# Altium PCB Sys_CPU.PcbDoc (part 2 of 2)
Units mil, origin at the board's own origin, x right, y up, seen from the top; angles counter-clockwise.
Board outline 2999.97 x 2496.97 mil, 4 copper layers (Top Layer, GND, POWER, Bottom Layer); 73 components, 87 nets, 428 pads, 131 vias.
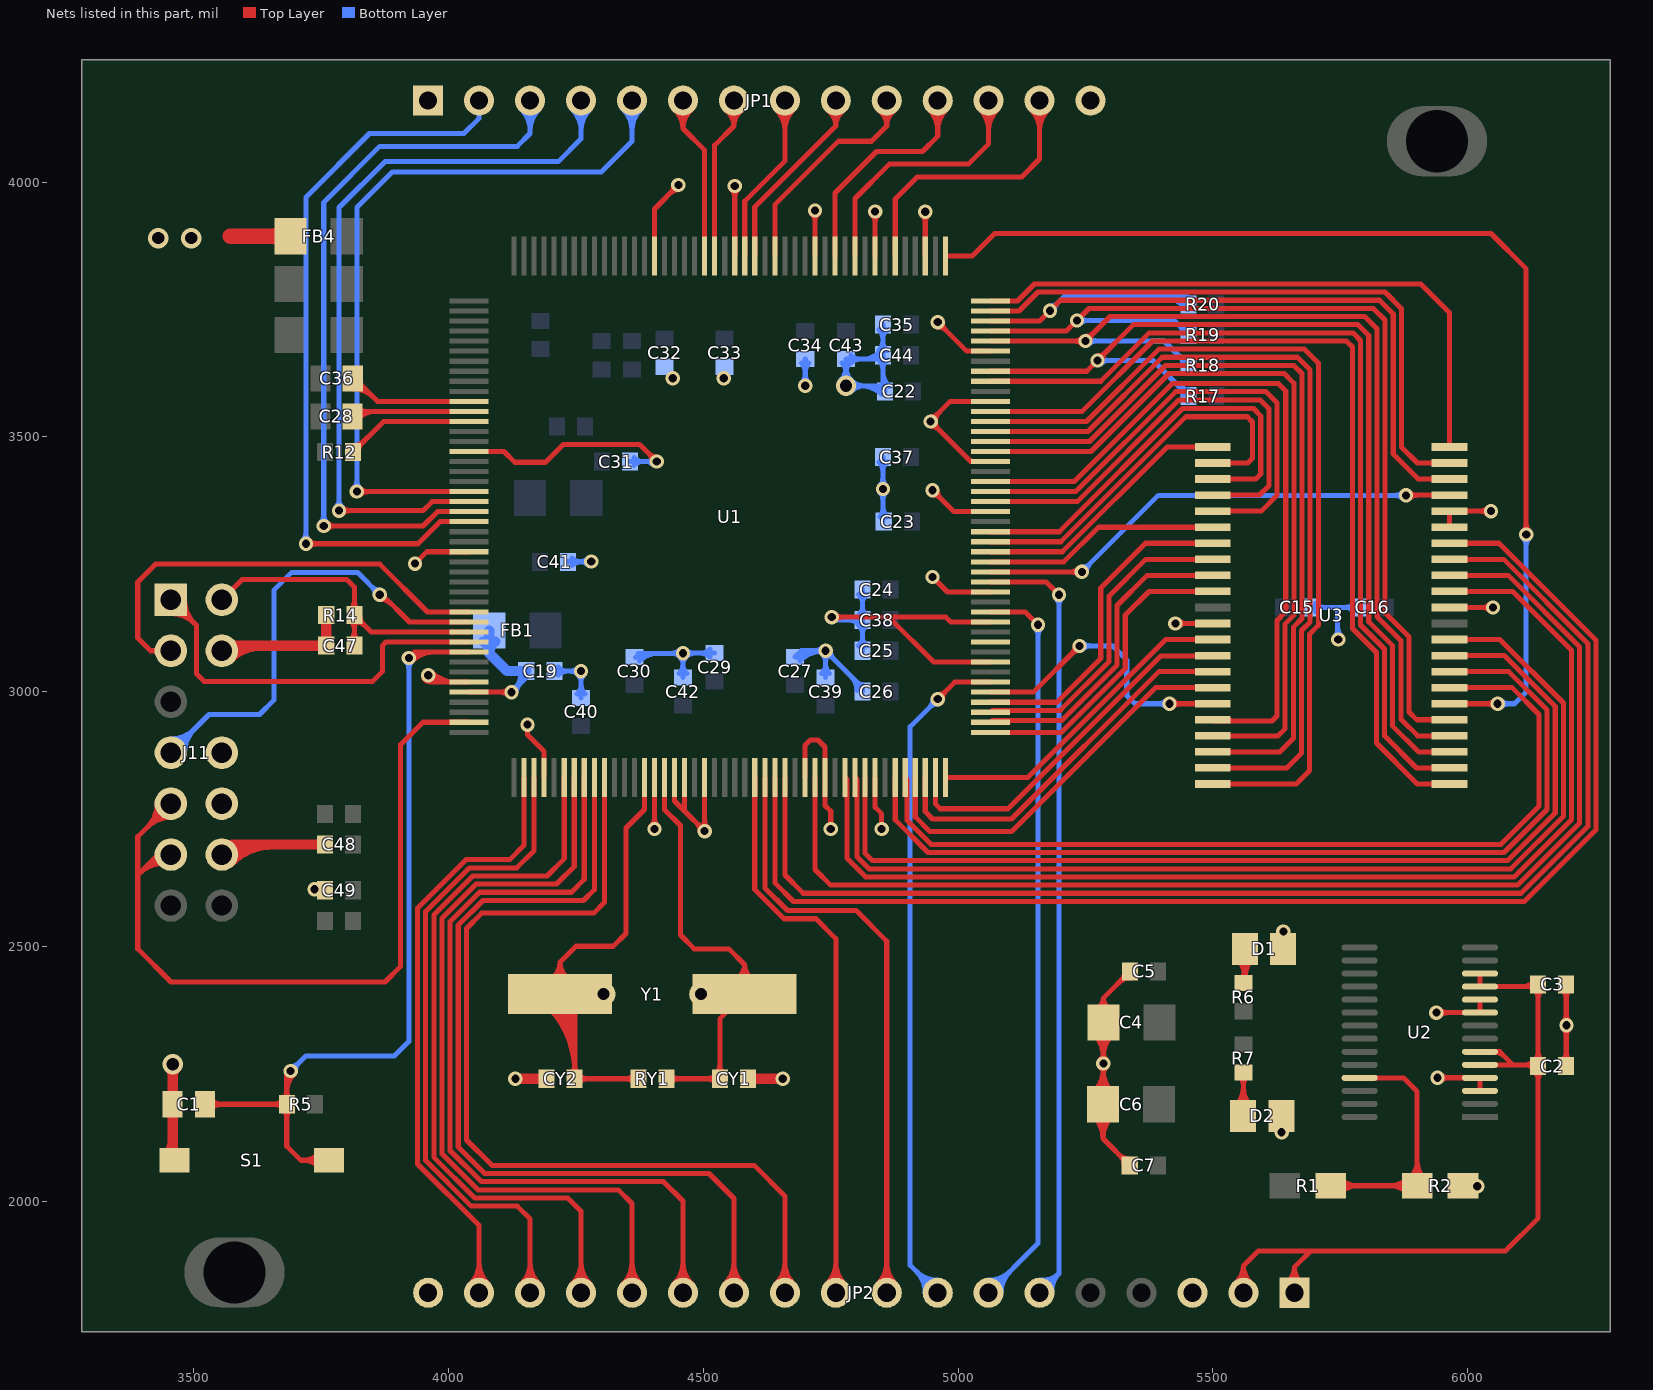
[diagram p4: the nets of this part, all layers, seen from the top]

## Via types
v1: diameter 28, hole 16, Top Layer to Bottom Layer, 105 vias
v2: diameter 40, hole 24, Top Layer to Bottom Layer, 25 vias
v3: diameter 40, hole 24, Top Layer to Bottom Layer, tented bottom, 1 vias

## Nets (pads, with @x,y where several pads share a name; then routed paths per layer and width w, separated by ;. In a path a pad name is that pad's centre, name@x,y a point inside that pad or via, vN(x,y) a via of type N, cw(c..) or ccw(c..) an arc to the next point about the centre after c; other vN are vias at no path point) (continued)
GND: C1.1 C2.1 C3.1 C4.2 C5.2 C6.2 C7.2 C15.1 C16.1 C19.1 C22.1 C23.1 C24.1 C25.1 C26.1 C27.1 C29.1 C30.1 C31.1 C32.1 C33.1 C34.1 C35.1 C37.1 C38.1 C39.1 C40.1 C41.1 C42.1 C43.1 C44.1 C47.1 C48.1 C49.1 CY1.1 CY2.1 D1.2 D2.2 FB4.1 J11.4 J11.8 J11.10 J11.12 JP1.1 JP1.14 JP2.3 JP2.18 R2.2 R14.2 S1.2 U1.3 U1.8 U1.14 U1.22 U1.30 U1.60 U1.70 U1.83 U1.92 U1.103 U1.105 U1.106 U1.108 U1.118 U1.120 U1.125 U1.140 U1.144 U1.147 U1.155 U1.160 U1.166 U1.171 U2.3 U2.4 U2.9 U2.10 U3.12 U3.34 U3.39 U3.40 | length 10653.8
  Top Layer w10: v1(3934,3251) 3957.29,3274.29 U1.70@4039.97,3274.29 ; v1@3952.22,3024.22 ccw(c3966.31,3038.31) 3966.31,3018.39 ; v1@3959.29,3031.29 ccw(c3990.45,3062.45) 3990.45,3018.39 ; v1@3966.36,3038.36 ccw(c4014.59,3086.59) U1.83@4014.59,3018.39 ; 3969,3018.39 U1.83@4039.97,3018.39 ; U1.60@4039.97,3471.14 4108.86,3471.14 4130,3450 4190,3450 4225,3485 4375,3485 v1(4408.54,3451.46) ; v1(4155,2935) 4155,2915 4187.6,2882.4 U1.92@4187.6,2831.38 ; v1@4397.77,2736.36 ccw(c4382.41,2751.73) 4404.14,2751.73 ccw(c4425.87,2751.73) v1@4410.5,2736.36 ; v1@4399.54,3451.46 ccw(c4377.81,3451.46) 4393.18,3466.82 ccw(c4408.54,3482.19) v1@4408.54,3460.46 ; v1(4404.14,2730) U1.103@4404.14,2831.38 ; U1.30@4404.14,3855 4404.14,3947.14 v1(4451,3994) ; v1@4442,3994 cw(c4420.27,3994) 4435.64,3978.64 cw(c4451,3963.27) v1@4451,3985 ; U1.105@4443.51,2831.38 4443.51,2785.06 4463.19,2765.37 ; U1.106@4463.19,2831.38 4463.19,2765.37 ; v1@4493.56,2726 ccw(c4471.84,2726) 4487.2,2741.36 ccw(c4502.56,2756.73) v1@4502.56,2735 ; v1@4496.2,2732.36 ccw(c4480.84,2747.73) 4502.56,2747.73 ccw(c4524.29,2747.73) v1@4508.93,2732.36 ; U1.108@4502.56,2831.38 v1(4502.56,2726) 4463.19,2765.37 ; v1@4555.25,3985.64 cw(c4539.89,3970.27) 4561.62,3970.27 cw(c4583.35,3970.27) v1@4567.98,3985.64 ; U1.22@4561.62,3855 v1(4561.62,3992) ; U1.118@4699.41,2831.38 4699.41,2894.41 4710,2905 4725,2905 4738.78,2891.22 U1.120@4738.78,2831.38 4738.78,2776.22 4750,2765 v1(4750,2730) ; v1@4712.73,3937.73 cw(c4697.37,3922.37) 4719.1,3922.37 cw(c4740.83,3922.37) v1@4725.46,3937.73 ; U1.14@4719.1,3855 v1(4719.1,3944.1) ; v1(4752,3146) 4976,3146 4985.5,3136.5 U1.144@5063.59,3136.5 ; v1@4758.36,3139.64 cw(c4773.73,3124.27) 4773.73,3146 cw(c4773.73,3167.73) v1@4758.36,3152.36 ; v1@4830.84,3935.84 cw(c4815.48,3920.48) 4837.21,3920.48 cw(c4858.94,3920.48) v1@4843.57,3935.84 ; U1.125@4837.21,2831.38 4837.21,2772.79 4850,2760 v1(4850,2730) ; U1.8@4837.21,3855 v1(4837.21,3942.21) ; 4866,3144 4952.24,3057.76 U1.140@5063.59,3057.76 ; v1@4929.27,3935.27 cw(c4913.91,3919.91) 4935.63,3919.91 cw(c4957.36,3919.91) v1@4942,3935.27 ; U1.3@4935.63,3855 v1(4935.63,3941.63) ; v1@4946.17,3521 cw(c4946.17,3499.27) 4961.54,3514.64 cw(c4976.9,3530) 4955.17,3530 cw(c4979.73,3530) 4962.36,3547.36 ; v1@4946.17,3539 ccw(c4946.17,3557.9) 4959.54,3544.54 ; v1(4950,3225) 4979.45,3195.55 U1.147@5063.59,3195.55 ; v1@4950,3386 cw(c4950,3364.27) 4965.36,3379.64 cw(c4980.73,3395) v1@4959,3395 ; v1(4950,3395) 4991.97,3353.03 U1.155@5063.59,3353.03 ; v1@4960,3716 cw(c4960,3694.27) 4975.36,3709.64 cw(c4990.73,3725) v1@4969,3725 ; v1(4960,3725) 5017.01,3667.99 U1.171@5063.59,3667.99 ; 5020.56,3455.61 ccw(c5030.59,3465.64) U1.160@5030.59,3451.46 ; U1.160@5063.59,3451.46 5024.71,3451.46 v1(4946.17,3530) 4946.17,3531.17 4984.57,3569.57 U1.166@5063.59,3569.57 ; C6.2@5265.59,2212.67 ccw(c5218.53,2259.73) v1@5285.08,2259.73 ; C6.2@5265.68,2167.23 cw(c5221.48,2122.56) 5284.32,2122.56 ; C4.2@5266.34,2328.01 cw(c5221.11,2282.78) 5285.08,2282.78 cw(c5349.04,2282.78) C4.2@5303.81,2328.01 ; C6.2@5272.66,2205.6 ccw(c5242.68,2235.58) 5285.08,2235.58 ; C6.2@5272.72,2174.34 cw(c5245.2,2146.53) 5284.32,2146.53 cw(c5323.45,2146.53) C6.2@5295.93,2174.34 ; C4.2@5272.92,2378.17 ccw(c5262.61,2398.13) 5285.08,2398.13 ; C4.2@5273.41,2335.08 cw(c5245.25,2306.92) 5285.08,2306.92 cw(c5324.9,2306.92) C4.2@5296.74,2335.08 ; v1@5278.71,2263.64 cw(c5263.35,2248.27) 5285.08,2248.27 cw(c5306.81,2248.27) v1@5291.44,2263.64 ; v1@5278.71,2276.36 ccw(c5263.35,2291.73) 5285.08,2291.73 ccw(c5306.81,2291.73) v1@5291.44,2276.36 ; 5285.08,2231.94 ccw(c5322.33,2231.94) C6.2@5295.99,2205.6 ; v1@5285.08,2256.08 ccw(c5346.47,2256.08) C6.2@5303.06,2212.67 ; C4.2@5297.23,2378.17 cw(c5307.54,2398.13) 5285.08,2398.13 ; C6.2@5302.96,2167.23 ccw(c5347.17,2122.56) 5284.32,2122.56 ; 5315.17,2091.71 ccw(c5336.88,2113.42) C7.2@5336.88,2082.72 ; 5315.93,2428.98 cw(c5337.64,2407.27) C5.2@5337.64,2437.97 ; 5319.93,2086.96 cw(c5304.94,2071.97) C7.2@5326.13,2071.97 ; 5320.68,2433.73 ccw(c5305.69,2448.72) C5.2@5326.89,2448.72 ; C7.2@5336.88,2070 5284.32,2122.56 ; C5.2@5337.64,2450.69 5285.08,2398.13 ; v1(5426.46,3133.54) U3.12@5505,3133.54 ; v1@5432.82,3127.18 cw(c5448.19,3111.81) 5448.19,3133.54 cw(c5448.19,3155.27) v1@5432.82,3139.91 ; v1(5938.72,2369.72) U2.9@6024.31,2369.72 U2.10@6024.31,2395.31 ; v1(5941,2242) 6024.08,2242 U2.4@6024.31,2241.77 U2.3@6024.31,2216.18 ; v1@5945.09,2363.36 cw(c5960.45,2348) 5960.45,2369.72 cw(c5960.45,2391.45) v1@5945.09,2376.09 ; v1@5947.36,2235.64 cw(c5962.73,2220.27) 5962.73,2242 cw(c5962.73,2263.73) v1@5947.36,2248.36 ; U3.39@5964.56,3322.52 U3.40@5964.56,3354.02 v1(6045.98,3354.02) ; U3.34@5969.56,3165.04 v1(6050,3165) v1(6050,3165) ; 6028.18,3165.04 cw(c6028.18,3143.18) v1@6043.64,3158.64 ; 6028.36,3165.04 ccw(c6028.36,3186.64) v1@6043.64,3171.36 ; v1@6039.62,3347.65 ccw(c6024.26,3332.29) 6024.26,3354.02 ccw(c6024.26,3375.74) v1@6039.62,3360.38 ; C2.1@6185.96,2274.57 ccw(c6167.61,2292.92) 6193.56,2292.92 ccw(c6219.51,2292.92) C2.1@6201.16,2274.57 ; C3.1@6185.96,2415.43 cw(c6167.61,2397.08) 6193.56,2397.08 cw(c6219.51,2397.08) C3.1@6201.16,2415.43 ; v1@6187.64,2338.64 cw(c6173.34,2324.34) 6193.56,2324.34 ; v1@6187.64,2351.36 ccw(c6173.34,2365.66) 6193.56,2365.66 ; C2.1@6193.56,2265 C3.1@6193.56,2425 ; 6193.56,2322.21 cw(c6216.79,2322.21) v1@6200.36,2338.64 ; 6193.56,2367.79 ccw(c6216.79,2367.79) v1@6200.36,2351.36 ; 5284.32,2122.56 C6.2@5284.32,2190 5285.08,2190.76 C4.2@5285.08,2350.69 5285.08,2398.13
  Top Layer w20: S1.2@3446.31,2089.63 ccw(c3416.88,2119.06) 3458.5,2119.06 ; v2@3451.43,2261.43 cw(c3434.36,2244.36) 3458.5,2244.36 cw(c3482.65,2244.36) v2@3465.58,2261.43 ; C1.1@3451.66,2177.25 cw(c3435.12,2160.71) 3458.5,2160.71 cw(c3481.89,2160.71) C1.1@3465.35,2177.25 ; C1.1@3451.66,2202.75 ccw(c3435.12,2219.29) 3458.5,2219.29 ccw(c3481.89,2219.29) C1.1@3465.35,2202.75 ; 3458.5,2106.71 ccw(c3482.65,2106.71) S1.2@3465.58,2089.63 ; v2(3458.5,2268.5) C1.1@3458.5,2190 3458.5,2083.35 S1.2@3461.85,2080 ; J11.12@3555,2680 3575,2700 C48.1@3757.44,2700 ; J11.4@3555,3080 3565,3090 C47.1@3759.88,3090 R14.2@3759.88,3150 ; J11.12@3556.41,2678.59 cw(c3608.11,2626.89) 3608.11,2700 ; J11.12@3570.56,2664.44 cw(c3656.4,2578.6) 3656.4,2700 ; J11.4@3570.56,3064.44 cw(c3632.26,3002.74) 3632.26,3090 ; v1(4131,2240) CY2.1@4192.44,2240 ; CY1.1@4587.56,2240 v1(4656,2240)
  Top Layer w30: 3571.43,3893.57 FB4.1@3689.88,3893.57 ; FB4.1@3678.22,3881.9 ccw(c3650.06,3853.74) 3650.06,3893.57 ccw(c3650.06,3933.39) FB4.1@3678.22,3905.23
  Bottom Layer w10: C19.1@4207.56,3040 v1(4260,3040) C40.1@4260,2987.56 ; C19.1@4215.16,3032.4 cw(c4233.51,3014.05) 4233.51,3040 cw(c4233.51,3065.95) C19.1@4215.16,3047.6 ; C41.1@4234.61,3254.61 4235,3255 v1(4280,3255) ; C41.1@4242.21,3247.01 cw(c4261.5,3227.71) 4261.5,3255 ; C41.1@4242.21,3262.21 ccw(c4259.61,3279.61) 4259.61,3255 ; C40.1@4252.4,2995.16 ccw(c4234.05,3013.51) 4260,3013.51 ccw(c4285.95,3013.51) C40.1@4267.6,2995.16 ; v1@4253.64,3046.36 cw(c4238.27,3061.73) 4238.27,3040 cw(c4238.27,3018.27) 4253.64,3033.64 cw(c4238.27,3018.27) 4260,3018.27 cw(c4281.73,3018.27) v1@4266.36,3033.64 ; v1@4273.64,3248.64 ccw(c4258.27,3233.27) 4258.27,3255 ccw(c4258.27,3276.73) v1@4273.64,3261.36 ; C31.1@4356.1,3451.46 v1(4408.54,3451.46) ; C31.1@4363.7,3443.86 cw(c4382.05,3425.51) 4382.05,3451.46 cw(c4382.05,3477.41) C31.1@4363.7,3459.06 ; C30.1@4367.27,3067.03 cw(c4386.51,3047.79) 4386.51,3075 ; C30.1@4372.21,3075 v1(4460,3075) ; C30.1@4374.34,3059.96 cw(c4410.65,3023.65) 4410.65,3075 ; v1@4402.18,3445.09 ccw(c4386.81,3429.73) 4386.81,3451.46 ccw(c4386.81,3473.19) v1@4402.18,3457.82 ; C42.1@4452.4,3035.16 ccw(c4434.05,3053.51) 4460,3053.51 ccw(c4485.95,3053.51) C42.1@4467.6,3035.16 ; v1@4453.64,3081.36 cw(c4438.27,3096.73) 4438.27,3075 cw(c4438.27,3053.27) 4453.64,3068.64 cw(c4438.27,3053.27) 4460,3053.27 cw(c4481.73,3053.27) 4466.36,3068.64 cw(c4482.48,3052.52) 4482.48,3075.31 ; C42.1@4460,3027.56 v1(4460,3075) ; v1@4466.36,3081.36 ccw(c4480.98,3095.98) 4480.98,3075.31 ; C29.1@4512.68,3067.71 ccw(c4494.33,3049.36) 4494.33,3075.31 ccw(c4494.33,3101.26) C29.1@4512.68,3082.91 ; C29.1@4522.25,3075.31 4460.31,3075.31 v1(4460,3075) ; C27.1@4680,3067.56 4692.44,3080 v1(4740,3080) ; C27.1@4682.5,3067.03 cw(c4713.81,3035.72) 4713.81,3080 ; C27.1@4689.57,3059.96 cw(c4737.95,3011.58) v1@4737.95,3080 ; C34.1@4692.4,3644.84 cw(c4674.05,3626.49) 4700,3626.49 cw(c4725.95,3626.49) C34.1@4707.6,3644.84 ; v1@4693.64,3606.36 ccw(c4678.27,3621.73) 4700,3621.73 ccw(c4721.73,3621.73) v1@4706.36,3606.36 ; v1(4700,3600) C34.1@4700,3652.44 ; C39.1@4732.4,3035.16 ccw(c4714.05,3053.51) 4740,3053.51 ccw(c4765.95,3053.51) C39.1@4747.6,3035.16 ; v1@4733.64,3086.36 cw(c4718.27,3101.73) 4718.27,3080 cw(c4718.27,3058.27) 4733.64,3073.64 cw(c4718.27,3058.27) 4740,3058.27 cw(c4761.73,3058.27) v1@4746.36,3073.64 ; C39.1@4740,3027.56 v1(4740,3080) ; v1@4740,3071 cw(c4740,3049.27) 4755.36,3064.64 cw(c4770.73,3080) v1@4749,3080 ; v1(4752,3146) 4758,3140 C38.1@4812.44,3140 ; v1@4758.36,3152.36 ccw(c4788.21,3182.21) 4788.21,3140 ; v2@4769.39,3610.61 ccw(c4743.79,3636.21) 4780,3636.21 ccw(c4816.21,3636.21) 4790.61,3610.61 ccw(c4816.21,3636.21) 4816.21,3600 ccw(c4816.21,3563.79) v2@4790.61,3589.39 ; C43.1@4772.4,3644.84 cw(c4754.05,3626.49) 4780,3626.49 cw(c4805.95,3626.49) C43.1@4787.6,3644.84 ; C43.1@4789.57,3644.84 cw(c4807.92,3626.49) 4807.92,3652.44 cw(c4807.92,3678.39) C43.1@4789.57,3660.04 ; 4790.14,3029.86 cw(c4762.25,3001.97) C26.1@4801.69,3001.97 ; C26.1@4803.64,3016.36 ccw(c4812.44,3025.17) C26.1@4812.44,3012.72 ; C25.1@4804.84,3089.57 ccw(c4786.49,3107.92) 4812.44,3107.92 ccw(c4838.39,3107.92) C25.1@4820.04,3089.57 ; C38.1@4804.84,3130.43 cw(c4786.49,3112.08) 4812.44,3112.08 cw(c4838.39,3112.08) C38.1@4820.04,3130.43 ; C38.1@4804.84,3132.4 ccw(c4786.49,3114.05) 4786.49,3140 ccw(c4786.49,3165.95) C38.1@4804.84,3147.6 ; C38.1@4804.84,3149.57 ccw(c4786.49,3167.92) 4812.44,3167.92 ccw(c4838.39,3167.92) C38.1@4820.04,3149.57 ; C24.1@4804.84,3190.43 cw(c4786.49,3172.08) 4812.44,3172.08 cw(c4838.39,3172.08) C24.1@4820.04,3190.43 ; 4809.55,3600 cw(c4809.55,3544.08) C22.1@4849.09,3583.62 ; C26.1@4812.44,3000 4812.44,3007.56 v1(4740,3080) ; C25.1@4812.44,3080 C38.1@4812.44,3140 ; C24.1@4812.44,3200 C38.1@4812.44,3140 ; 4813,3652.44 ccw(c4813,3697.48) C44.1@4844.84,3665.63 ; 4833.69,3600 cw(c4833.69,3568.22) C22.1@4856.16,3590.69 ; C44.1@4837.14,3652.44 ccw(c4837.14,3673.33) C44.1@4851.91,3658.56 ; C37.1@4844.84,3450.43 cw(c4826.49,3432.08) 4852.44,3432.08 cw(c4878.39,3432.08) C37.1@4860.04,3450.43 ; C44.1@4844.84,3650.43 cw(c4826.49,3632.08) 4852.44,3632.08 cw(c4878.39,3632.08) C44.1@4860.04,3650.43 ; C44.1@4844.84,3669.57 ccw(c4826.49,3687.92) 4852.44,3687.92 ccw(c4878.39,3687.92) C44.1@4860.04,3669.57 ; C35.1@4844.84,3710.43 cw(c4826.49,3692.08) 4852.44,3692.08 cw(c4878.39,3692.08) C35.1@4860.04,3710.43 ; C22.1@4845.94,3600 v2(4780,3600) C43.1@4780,3652.44 4844.88,3652.44 C44.1@4852.44,3660 ; v1@4846.08,3391.08 cw(c4830.71,3375.71) 4852.44,3375.71 cw(c4874.17,3375.71) v1@4858.8,3391.08 ; v1@4846.08,3403.8 ccw(c4830.71,3419.17) 4852.44,3419.17 ccw(c4874.17,3419.17) v1@4858.8,3403.8 ; C23.1@4846.49,3342.92 ccw(c4832.13,3357.28) 4852.44,3357.28 ; C22.1@4849.09,3598.82 ccw(c4841.01,3606.9) C22.1@4852.44,3606.9 ; C23.1@4852.44,3335 v1(4852.44,3397.44) C37.1@4852.44,3460 ; 4852.44,3365.25 ccw(c4884.03,3365.25) C23.1@4861.69,3342.92 ; 4852.44,3627.43 ccw(c4892.91,3627.43) C22.1@4864.29,3598.82 ; C35.1@4852.44,3720 C44.1@4852.44,3660 ; C22.1@4856.69,3589.25 4852.44,3593.5 C44.1@4852.44,3660 ; C15.1@5692.56,3165 C16.1@5785,3165 ; C15.1@5700.16,3157.4 cw(c5718.51,3139.05) 5718.51,3165 cw(c5718.51,3190.95) C15.1@5700.16,3172.6 ; v1@5739.64,3108.36 ccw(c5726.69,3121.31) 5745,3121.31 ; v1@5745,3102 5745,3161 ; 5745,3126.14 ccw(c5770.14,3126.14) v1@5752.36,3108.36 ; C16.1@5777.4,3157.4 ccw(c5759.05,3139.05) 5759.05,3165 ccw(c5759.05,3190.95) C16.1@5777.4,3172.6
  other v1: 6019,2029 5635,2135 5285.08,2270 6194,2345 5638.44,2529 3737,2612 3960,3032 5746,3102 4440,3615 4540,3615
  other v2: 3430,3890 3495,3890
GPIO1: JP1.13 U1.6 | length 690.6
  Top Layer w10: U1.6@4876.58,3855 4876.58,3966.58 4920,4010 5125,4010 5160,4045 JP1.13@5160,4160 ; JP1.13@5142.66,4142.66 cw(c5100.79,4100.79) 5160,4100.79 cw(c5219.21,4100.79) JP1.13@5177.34,4142.66 ; JP1.13@5149.73,4149.73 cw(c5124.93,4124.93) 5160,4124.93 cw(c5195.07,4124.93) JP1.13@5170.27,4149.73
GPIO3: JP1.12 U1.10 | length 652.5
  Top Layer w10: U1.10@4797.84,3855 4797.84,3967.84 4865,4035 5020,4035 5060,4075 JP1.12@5060,4160 ; JP1.12@5042.66,4142.66 cw(c5000.79,4100.79) 5060,4100.79 cw(c5119.21,4100.79) JP1.12@5077.34,4142.66 ; JP1.12@5049.73,4149.73 cw(c5024.93,4124.93) 5060,4124.93 cw(c5095.07,4124.93) JP1.12@5070.27,4149.73
GPIO5: JP1.11 U1.12 | length 589.3
  Top Layer w10: U1.12@4758.47,3855 4758.47,3978.47 4840,4060 4930,4060 4960,4090 JP1.11@4960,4160 ; JP1.11@4942.66,4142.66 cw(c4900.79,4100.79) 4960,4100.79 cw(c5019.21,4100.79) JP1.11@4977.34,4142.66 ; JP1.11@4949.73,4149.73 cw(c4924.93,4124.93) 4960,4124.93 cw(c4995.07,4124.93) JP1.11@4970.27,4149.73
GPIO50: JP2.17 U1.90 | length 1346.5
  Top Layer w10: JP2.17@4042.66,1837.34 ccw(c4000.79,1879.21) 4060,1879.21 ccw(c4119.21,1879.21) JP2.17@4077.34,1837.34 ; JP2.17@4049.73,1830.27 ccw(c4024.93,1855.07) 4060,1855.07 ccw(c4095.07,1855.07) JP2.17@4070.27,1830.27 ; JP2.17@4060,1820 4060,1951.86 3939,2072.86 3939,2574.76 4034.24,2670 4120,2670 4148.23,2698.23 U1.90@4148.23,2831.38
GPIO51: JP2.16 U1.91 | length 1440.2
  Top Layer w10: JP2.16@4142.66,1837.34 ccw(c4100.79,1879.21) 4160,1879.21 ccw(c4219.21,1879.21) JP2.16@4177.34,1837.34 ; JP2.16@4149.73,1830.27 ccw(c4124.93,1855.07) 4160,1855.07 ccw(c4195.07,1855.07) JP2.16@4170.27,1830.27 ; JP2.16@4160,1820 4160,1965 4135,1990 4044.49,1990 3955,2079.49 3955,2568.14 4040.86,2654 4134,2654 4167.92,2687.92 U1.91@4167.92,2831.38
GPIO52: JP2.15 U1.94 | length 1577.6
  Top Layer w10: U1.94@4226.97,2831.38 4226.97,2671.97 4193,2638 4047.49,2638 3971,2561.51 3971,2086.12 4051.12,2006 4234,2006 4260,1980 JP2.15@4260,1820 ; JP2.15@4242.66,1837.34 ccw(c4200.79,1879.21) 4260,1879.21 ccw(c4319.21,1879.21) JP2.15@4277.34,1837.34 ; JP2.15@4249.73,1830.27 ccw(c4224.93,1855.07) 4260,1855.07 ccw(c4295.07,1855.07) JP2.15@4270.27,1830.27
GPIO53: JP2.14 U1.95 | length 1675.3
  Top Layer w10: U1.95@4246.66,2831.38 4246.66,2656.66 4212,2622 4054.12,2622 3987,2554.88 3987,2092.75 4057.75,2022 4333,2022 4360,1995 JP2.14@4360,1820 ; JP2.14@4342.66,1837.34 ccw(c4300.79,1879.21) 4360,1879.21 ccw(c4419.21,1879.21) JP2.14@4377.34,1837.34 ; JP2.14@4349.73,1830.27 ccw(c4324.93,1855.07) 4360,1855.07 ccw(c4395.07,1855.07) JP2.14@4370.27,1830.27
MCLKXA: JP1.3 U1.66 | length 1673.9
  Top Layer w10: v1(3755,3325) 3950,3325 3978.03,3353.03 U1.66@4039.97,3353.03 ; v1@3761.36,3318.64 cw(c3776.73,3303.27) 3776.73,3325 cw(c3776.73,3346.73) v1@3761.36,3331.36
  Bottom Layer w10: v1@3748.64,3331.36 ccw(c3733.27,3346.73) 3755,3346.73 ccw(c3776.73,3346.73) v1@3761.36,3331.36 ; v1(3755,3325) 3755,3960 3865,4070 4135,4070 4160,4095 JP1.3@4160,4160 ; JP1.3@4142.66,4142.66 cw(c4100.79,4100.79) 4160,4100.79 cw(c4219.21,4100.79) JP1.3@4177.34,4142.66 ; JP1.3@4149.73,4149.73 cw(c4124.93,4124.93) 4160,4124.93 cw(c4195.07,4124.93) JP1.3@4170.27,4149.73
MCLKXB: JP1.6 U1.25 | length 454.6
  Top Layer w10: JP1.6@4443.61,4141.75 cw(c4410.61,4105) 4460,4105 ; JP1.6@4450.29,4149.19 cw(c4430.74,4127.43) 4460,4127.43 cw(c4489.26,4127.43) JP1.6@4469.71,4149.19 ; JP1.6@4460,4160 4460,4105 ; JP1.6@4476.39,4141.75 ccw(c4509.39,4105) 4460,4105 ; U1.25@4502.56,3855 4502.56,4062.44 4460,4105
MDRA: JP1.4 U1.65 | length 1674.6
  Top Layer w10: v1@3790,3355 3950,3355 3967.72,3372.72 U1.65@4039.97,3372.72 ; v1@3791.36,3348.64 cw(c3806.73,3333.27) 3806.73,3355 cw(c3806.73,3376.73) v1@3791.36,3361.36
  Bottom Layer w10: v1@3778.64,3361.36 ccw(c3763.27,3376.73) 3785,3376.73 ccw(c3806.73,3376.73) v1@3791.36,3361.36 ; v1(3785,3355) 3785,3950 3875,4040 4215,4040 4260,4085 JP1.4@4260,4160 ; JP1.4@4242.66,4142.66 cw(c4200.79,4100.79) 4260,4100.79 cw(c4319.21,4100.79) JP1.4@4277.34,4142.66 ; JP1.4@4249.73,4149.73 cw(c4224.93,4124.93) 4260,4124.93 cw(c4295.07,4124.93) JP1.4@4270.27,4149.73
MDRB: JP1.7 U1.24 | length 433
  Top Layer w10: U1.24@4522.25,3855 4522.25,4072.25 4560,4110 ; JP1.7@4544.99,4140.6 cw(c4521.31,4110) 4560,4110 ; JP1.7@4551.11,4148.51 cw(c4537.08,4130.39) 4560,4130.39 cw(c4582.92,4130.39) JP1.7@4568.89,4148.51 ; JP1.7@4560,4160 4560,4110 ; JP1.7@4575.01,4140.6 ccw(c4598.69,4110) 4560,4110
MDXA: JP1.5 U1.64 | length 1667.8
  Top Layer w10: v1(3820,3392.4) U1.64@4039.97,3392.4 ; v1@3826.36,3386.04 cw(c3841.73,3370.67) 3841.73,3392.4 cw(c3841.73,3414.13) v1@3826.36,3398.77
  Bottom Layer w10: v1@3813.64,3398.77 ccw(c3798.27,3414.13) 3820,3414.13 ccw(c3841.73,3414.13) v1@3826.36,3398.77 ; v1(3820,3392.4) 3820,3950 3890,4020 4300,4020 4360,4080 JP1.5@4360,4160 ; JP1.5@4342.66,4142.66 cw(c4300.79,4100.79) 4360,4100.79 cw(c4419.21,4100.79) JP1.5@4377.34,4142.66 ; JP1.5@4349.73,4149.73 cw(c4324.93,4124.93) 4360,4124.93 cw(c4395.07,4124.93) JP1.5@4370.27,4149.73
MDXB: JP1.8 U1.21 | length 485.7
  Top Layer w10: U1.21@4581.3,3855 4581.3,3962.3 4660,4041 JP1.8@4660,4160 ; JP1.8@4642.66,4142.66 cw(c4600.79,4100.79) 4660,4100.79 cw(c4719.21,4100.79) JP1.8@4677.34,4142.66 ; JP1.8@4649.73,4149.73 cw(c4624.93,4124.93) 4660,4124.93 cw(c4695.07,4124.93) JP1.8@4670.27,4149.73
MFSXA: JP1.2 U1.67 | length 1520.4
  Top Layer w10: v1@3725,3290 3940,3290 3983.35,3333.35 U1.67@4039.97,3333.35 ; v1@3726.36,3283.64 cw(c3741.73,3268.27) 3741.73,3290 cw(c3741.73,3311.73) v1@3726.36,3296.36
  Bottom Layer w10: v1@3713.64,3296.36 ccw(c3698.27,3311.73) 3720,3311.73 ccw(c3741.73,3311.73) v1@3726.36,3296.36 ; v1(3720,3290) 3720,3970 3845,4095 4030,4095 4060,4125 JP1.2@4060,4160
NetC28_2: C28.2 U1.56 | length 293.8
  Top Layer w10: C28.2@3814.81,3542.59 cw(c3832.41,3524.99) 3832.41,3549.88 ; C28.2@3821.38,3549.88 U1.56@4039.97,3549.88 ; C28.2@3821.88,3535.52 cw(c3856.55,3500.85) 3856.55,3549.88 ; C28.2@3821.88,3556.29 ccw(c3837.35,3571.76) 3837.35,3549.88
NetC36_2: C36.2 U1.55 | length 329.1
  Top Layer w10: C36.2@3811.93,3593.98 cw(c3811.93,3535.81) 3853.06,3576.94 ; C36.2@3811.93,3603.98 cw(c3811.93,3569.95) 3835.99,3594.01 ; C36.2@3811.93,3614.57 3815.43,3614.57 3860.43,3569.57 U1.55@4039.97,3569.57 ; C36.2@3826.61,3608.66 ccw(c3839.35,3608.66) C36.2@3830.34,3599.66
NetCY1_2: CY1.2 RY1.2 U1.104 Y1.1 | length 1059.9
  Top Layer w10: U1.104@4423.82,2831.38 4423.82,2768.18 4455,2737 4455,2522 4482,2495 4550,2495 4580.87,2464.13 ; RY1.2@4427.56,2240 CY1.2@4532.44,2240 4532.44,2357.64 Y1.1@4580.87,2406.06 4580.87,2464.13 ; RY1.2@4435.16,2232.4 cw(c4453.51,2214.05) 4453.51,2240 cw(c4453.51,2265.95) RY1.2@4435.16,2247.6 ; CY1.2@4524.84,2232.4 ccw(c4506.49,2214.05) 4506.49,2240 ccw(c4506.49,2265.95) CY1.2@4524.84,2247.6 ; CY1.2@4524.84,2249.57 ccw(c4506.49,2267.92) 4532.44,2267.92 ccw(c4558.39,2267.92) CY1.2@4540.04,2249.57 ; Y1.1@4564.33,2436.19 ccw(c4549,2464.13) 4580.87,2464.13 ; Y1.1@4569.14,2427.43 ccw(c4558.27,2447.24) 4580.87,2447.24 ccw(c4603.46,2447.24) Y1.1@4592.59,2427.43 ; Y1.1@4597.4,2436.19 cw(c4612.73,2464.13) 4580.87,2464.13
NetCY2_2: CY2.2 RY1.1 U1.102 Y1.2 | length 1670.2
  Top Layer w10: Y1.2@4194.36,2381.76 cw(c4065.92,2253.32) CY2.2@4247.56,2253.32 ; Y1.2@4200.22,2435.06 ccw(c4178.85,2468.66) 4218.66,2468.66 ; Y1.2@4201.43,2388.83 cw(c4090.06,2277.46) 4247.56,2277.46 ; Y1.2@4205.58,2426.63 ccw(c4190.43,2450.45) 4218.66,2450.45 ccw(c4246.89,2450.45) Y1.2@4231.74,2426.63 ; Y1.2@4208.5,2395.9 cw(c4114.2,2301.61) 4247.56,2301.61 ; Y1.2@4215.57,2402.97 cw(c4138.35,2325.75) 4247.56,2325.75 ; Y1.2@4222.64,2410.04 cw(c4162.49,2349.89) 4247.56,2349.89 ; Y1.2@4229.71,2417.12 cw(c4186.63,2374.03) Y1.2@4247.56,2374.03 ; Y1.2@4237.11,2435.06 cw(c4258.48,2468.66) 4218.66,2468.66 ; CY2.2@4239.96,2249.57 ccw(c4221.61,2267.92) 4247.56,2267.92 ccw(c4273.51,2267.92) CY2.2@4255.16,2249.57 ; CY2.2@4255.16,2232.4 cw(c4273.51,2214.05) 4273.51,2240 cw(c4273.51,2265.95) CY2.2@4255.16,2247.6 ; RY1.1@4364.84,2232.4 ccw(c4346.49,2214.05) 4346.49,2240 ccw(c4346.49,2265.95) RY1.1@4364.84,2247.6 ; RY1.1@4372.44,2240 CY2.2@4247.56,2240 4247.56,2377.17 Y1.2@4218.66,2406.06 4218.66,2468.66 ; U1.102@4384.45,2831.38 4384.45,2768.45 4348,2732 4348,2525 4323,2500 4250,2500 4218.66,2468.66
NetD1_1: D1.1 R6.1 | length 187.5
  Top Layer w10: D1.1@5548.48,2474.53 cw(c5513.33,2439.38) 5563.04,2439.38 cw(c5612.75,2439.38) D1.1@5577.6,2474.53 ; R6.1@5554.37,2435.16 ccw(c5533.43,2456.09) 5563.04,2456.09 ; R6.1@5560,2427.56 5563.04,2430.6 D1.1@5563.04,2495 ; 5563.04,2450.92 ccw(c5585.33,2450.92) R6.1@5569.57,2435.16
NetD2_1: D2.1 R7.1 | length 239
  Top Layer w10: D2.1@5545.04,2187.46 ccw(c5508.92,2223.58) 5560,2223.58 ; D2.1@5552.11,2180.39 ccw(c5533.06,2199.44) 5560,2199.44 ; R7.1@5552.4,2244.84 cw(c5534.05,2226.49) 5560,2226.49 cw(c5585.95,2226.49) R7.1@5567.6,2244.84 ; D2.1@5559.6,2167 D2.1@5560,2167.4 ; 5560,2221.65 ccw(c5608.34,2221.65) D2.1@5574.16,2187.46 ; R7.1@5560,2252.44 D2.1@5560,2167.4 ; D2.1@5569.44,2176.84 D2.1@5560,2167.4
NetR1_2: R1.2 R2.1 U2.25 | length 706.5
  Top Layer w10: R1.2@5731,2030 R2.1@5901,2030 5901,2215 5874.23,2241.77 U2.25@5788.09,2241.77 ; R1.2@5750.14,2015.86 cw(c5784.28,1981.72) 5784.28,2030 cw(c5784.28,2078.28) R1.2@5750.14,2044.14 ; R2.1@5881.86,2015.86 ccw(c5847.72,1981.72) 5847.72,2030 ccw(c5847.72,2078.28) R2.1@5881.86,2044.14 ; R2.1@5886.86,2044.14 ccw(c5852.72,2078.28) 5901,2078.28 ccw(c5949.28,2078.28) R2.1@5915.14,2044.14
NetR12_2: R12.2 U1.57 | length 293.1
  Top Layer w10: R12.2@3812.56,3470 3872.76,3530.2 U1.57@4039.97,3530.2 ; R12.2@3812.56,3482.72 ccw(c3812.56,3513.42) 3834.27,3491.71 ; R12.2@3823.31,3471.97 cw(c3844.5,3471.97) 3829.52,3486.96
SCIRXDA: JP2.7 U1.145 | length 1637.3
  Top Layer w10: U1.145@5063.59,3156.18 5131.82,3156.18 v1(5157,3131)
  Bottom Layer w10: JP2.7@5060,1820 5157,1917 v1(5157,3131) ; JP2.7@5060,1834.53 ccw(c5060,1869.6) 5084.8,1844.8 ccw(c5109.6,1820) JP2.7@5074.53,1820 ; JP2.7@5060,1844.53 ccw(c5060,1903.74) 5101.87,1861.87 ccw(c5143.74,1820) JP2.7@5084.53,1820 ; v1@5150.64,3124.64 cw(c5135.27,3109.27) 5157,3109.27 cw(c5178.73,3109.27) v1@5163.36,3124.64
SCIRXDB: JP1.9 U1.20 | length 483.3
  Top Layer w10: U1.20@4600.99,3855 4600.99,3950.99 4760,4110 ; JP1.9@4744.99,4140.6 cw(c4721.31,4110) 4760,4110 ; JP1.9@4751.11,4148.51 cw(c4737.08,4130.39) 4760,4130.39 cw(c4782.92,4130.39) JP1.9@4768.89,4148.51 ; JP1.9@4760,4160 4760,4110 ; JP1.9@4775.01,4140.6 ccw(c4798.69,4110) 4760,4110
SCIRXDC: JP2.10 U1.113 | length 1262
  Top Layer w10: U1.113@4600.99,2831.38 4600.99,2611.38 4658.37,2554 4721,2554 4760,2515 JP2.10@4760,1820 ; JP2.10@4742.66,1837.34 ccw(c4700.79,1879.21) 4760,1879.21 ccw(c4819.21,1879.21) JP2.10@4777.34,1837.34 ; JP2.10@4749.73,1830.27 ccw(c4724.93,1855.07) 4760,1855.07 ccw(c4795.07,1855.07) JP2.10@4770.27,1830.27
SCITXDA: JP2.6 U1.148 | length 1691.8
  Top Layer w10: U1.148@5063.59,3215.24 5172.76,3215.24 v1(5198,3190)
  Bottom Layer w10: JP2.6@5160,1820 5198,1858 ; JP2.6@5161.03,1834.49 ccw(c5162.99,1862.02) 5182.51,1842.51 ccw(c5202.02,1822.99) JP2.6@5174.49,1821.03 ; JP2.6@5161.74,1844.47 ccw(c5165.04,1890.95) 5198,1858 ; JP2.6@5184.47,1821.74 cw(c5230.95,1825.04) 5198,1858 ; v1@5191.64,3183.64 cw(c5176.27,3168.27) 5198,3168.27 cw(c5219.73,3168.27) v1@5204.36,3183.64 ; v1(5198,3190) 5198,1858
SCITXDB: JP1.10 U1.18 | length 546.5
  Top Layer w10: U1.18@4640.36,3855 4640.36,3955.36 4765,4080 4830,4080 4860,4110 ; JP1.10@4844.99,4140.6 cw(c4821.31,4110) 4860,4110 ; JP1.10@4851.11,4148.51 cw(c4837.08,4130.39) 4860,4130.39 cw(c4882.92,4130.39) JP1.10@4868.89,4148.51 ; JP1.10@4860,4160 4860,4110 ; JP1.10@4875.01,4140.6 ccw(c4898.69,4110) 4860,4110
SCITXDC: JP2.9 U1.114 | length 1337.7
  Top Layer w10: U1.114@4620.67,2831.38 4620.67,2614.33 4665,2570 4800,2570 4860,2510 JP2.9@4860,1820 ; JP2.9@4842.66,1837.34 ccw(c4800.79,1879.21) 4860,1879.21 ccw(c4919.21,1879.21) JP2.9@4877.34,1837.34 ; JP2.9@4849.73,1830.27 ccw(c4824.93,1855.07) 4860,1855.07 ccw(c4895.07,1855.07) JP2.9@4870.27,1830.27
SPICLKA: JP2.11 U1.98 | length 1961.1
  Top Layer w10: U1.98@4305.71,2831.38 4305.71,2585.71 4285,2565 4065,2565 4035,2535 4035,2120 4085,2070 4600,2070 4660,2010 JP2.11@4660,1820 ; JP2.11@4642.66,1837.34 ccw(c4600.79,1879.21) 4660,1879.21 ccw(c4719.21,1879.21) JP2.11@4677.34,1837.34 ; JP2.11@4649.73,1830.27 ccw(c4624.93,1855.07) 4660,1855.07 ccw(c4695.07,1855.07) JP2.11@4670.27,1830.27
SPIMISOA: JP2.12 U1.97 | length 1867.7
  Top Layer w10: U1.97@4286.03,2831.38 4286.03,2611.03 4265,2590 4067.37,2590 4019,2541.63 4019,2106 4071,2054 4511,2054 4560,2005 JP2.12@4560,1820 ; JP2.12@4542.66,1837.34 ccw(c4500.79,1879.21) 4560,1879.21 ccw(c4619.21,1879.21) JP2.12@4577.34,1837.34 ; JP2.12@4549.73,1830.27 ccw(c4524.93,1855.07) 4560,1855.07 ccw(c4595.07,1855.07) JP2.12@4570.27,1830.27
SPIMOSIA: JP2.13 U1.96 | length 1772.9
  Top Layer w10: U1.96@4266.34,2831.38 4266.34,2631.34 4241,2606 4060.75,2606 4003,2548.25 4003,2099.37 4064.37,2038 4422,2038 4460,2000 JP2.13@4460,1820 ; JP2.13@4442.66,1837.34 ccw(c4400.79,1879.21) 4460,1879.21 ccw(c4519.21,1879.21) JP2.13@4477.34,1837.34 ; JP2.13@4449.73,1830.27 ccw(c4424.93,1855.07) 4460,1855.07 ccw(c4495.07,1855.07) JP2.13@4470.27,1830.27
TCK: J11.9 J11.11 U1.87 | length 1859.4
  Top Layer w10: 3392.05,2642.05 cw(c3444.19,2589.91) J11.11@3452.97,2663.12 ; 3406.6,2656.6 cw(c3447.31,2615.89) J11.11@3454.17,2673.05 ; 3421.15,2671.15 cw(c3450.42,2641.87) J11.11@3455.36,2682.98 ; J11.9@3428,2780 cw(c3362.82,2780) 3408.91,2733.91 cw(c3455,2687.82) J11.9@3455,2753 ; J11.9@3438,2780 cw(c3396.96,2780) 3425.98,2750.98 cw(c3455,2721.96) J11.9@3455,2763 ; J11.11@3455,2680 3430,2680 3390,2640 ; J11.9@3455,2780 3390,2715 3390,2640 ; U1.87@4039.97,2939.65 3949.65,2939.65 3906,2896 3906,2461 3875,2430 3455,2430 3390,2495 3390,2640
TDI: J11.3 U1.76 | length 888.7
  Top Layer w10: J11.3@3455,3080 3415,3080 3390,3105 3390,3215 3425,3250 3610,3250 3865,3250 3958.82,3156.18 U1.76@4039.97,3156.18
TDO: J11.7 U1.77 | length 1126
  Top Layer w10: v1@3865,3181 cw(c3865,3147.2) 3888.9,3171.1 ; v1(3865,3190) 3870,3190 3923.5,3136.5 U1.77@4039.97,3136.5
  Bottom Layer w10: J11.7@3455,2880 3530,2955 3629,2955 3657,2983 3657,3199 3692,3234 3821,3234 v1(3865,3190) ; J11.7@3455,2897 ccw(c3455,2938.04) 3484.02,2909.02 ccw(c3513.04,2880) J11.7@3472,2880 ; J11.7@3455,2907 ccw(c3455,2972.18) 3501.09,2926.09 ccw(c3547.18,2880) J11.7@3482,2880 ; v1@3856,3190 ccw(c3834.27,3190) 3849.64,3205.36 ccw(c3865,3220.73) v1@3865,3199
TMS: J11.1 U1.79 | length 935.6
  Top Layer w10: J11.1@3455,3153 cw(c3455,3087.82) 3501.09,3133.91 cw(c3547.18,3180) J11.1@3482,3180 ; J11.1@3455,3163 cw(c3455,3121.96) 3484.02,3150.98 cw(c3513.04,3180) J11.1@3472,3180 ; J11.1@3455,3180 3505,3130 3505,3035 3520,3020 3851,3020 3870,3039 3870,3090 3877.13,3097.13 U1.79@4039.97,3097.13
TRSTN: C47.2 J11.2 R14.1 U1.78 | length 804
  Top Layer w10: J11.2@3555,3180 3595,3220 3800,3220 3815,3205 R14.1@3815,3150 ; C47.2@3807.4,3099.57 ccw(c3789.05,3117.92) 3815,3117.92 ccw(c3840.95,3117.92) C47.2@3822.6,3099.57 ; R14.1@3807.4,3140.43 cw(c3789.05,3122.08) 3815,3122.08 cw(c3840.95,3122.08) R14.1@3822.6,3140.43 ; R14.1@3807.4,3159.57 ccw(c3789.05,3177.92) 3815,3177.92 ccw(c3840.95,3177.92) R14.1@3822.6,3159.57 ; R14.1@3815,3137.28 cw(c3815,3106.58) 3836.71,3128.29 ; C47.2@3818.19,3086.81 C47.2@3815,3090 R14.1@3815,3150 ; R14.1@3825.75,3148.03 ccw(c3846.94,3148.03) 3831.96,3133.04 ; U1.78@4039.97,3116.81 3848.19,3116.81 R14.1@3815,3150
VCC5IN: C2.2 C3.2 JP2.1 JP2.2 U2.5 U2.6 U2.11 U2.12 | length 2023.8
  Top Layer w10: JP2.2@5544.13,1838.7 ccw(c5515.01,1873) 5560,1873 ; JP2.2@5550.6,1831.07 ccw(c5533.35,1851.39) 5560,1851.39 ccw(c5586.65,1851.39) JP2.2@5569.4,1831.07 ; JP2.2@5560,1820 5560,1873 ; JP2.2@5575.87,1838.7 cw(c5604.99,1873) 5560,1873 ; JP2.1@5644.99,1839.4 ccw(c5621.31,1870) 5660,1870 ; JP2.1@5651.11,1831.49 ccw(c5637.08,1849.61) 5660,1849.61 ccw(c5682.92,1849.61) JP2.1@5668.89,1831.49 ; JP2.1@5660,1820 5660,1870 ; JP2.1@5675.01,1839.4 cw(c5698.69,1870) 5660,1870 ; U2.5@6024.31,2267.36 6088.64,2267.36 ; U2.6@6024.31,2292.95 6063.05,2292.95 6088.64,2267.36 ; U2.12@6024.31,2446.5 U2.11@6024.31,2420.91 C3.2@6129.47,2420.91 ; U2.6@6053.83,2292.05 cw(c6053.83,2267.61) 6071.11,2284.89 ; U2.6@6054.06,2292.07 cw(c6057.58,2278.27) 6067.65,2288.35 ; 6107.36,2420.91 ccw(c6107.36,2454.11) C3.2@6130.84,2430.63 ; 6111.54,2267.36 cw(c6111.54,2240.07) C2.2@6130.84,2259.37 ; 6113.44,2267.36 ccw(c6113.44,2291.97) 6130.84,2274.57 ccw(c6112.49,2292.92) 6138.44,2292.92 ccw(c6164.39,2292.92) C2.2@6146.04,2274.57 ; 6117.62,2420.91 cw(c6117.62,2402.21) 6130.84,2415.43 cw(c6112.49,2397.08) 6138.44,2397.08 cw(c6164.39,2397.08) C3.2@6146.04,2415.43 ; C2.2@6130.84,2255.43 cw(c6112.49,2237.08) 6138.44,2237.08 cw(c6164.39,2237.08) C2.2@6146.04,2255.43 ; C3.2@6138.44,2425 C2.2@6138.44,2269.72 ; 5560,1873 5589,1902 5692,1902 ; 5660,1870 5692,1902 ; 5692,1902 6074,1902 6138.44,1966.44 C2.2@6138.44,2265 C2.2@6138.44,2267.36 ; 6088.64,2267.36 C2.2@6138.44,2267.36 ; C2.2@6138.44,2267.36 6140.8,2267.36 C2.2@6138.44,2269.72 ; C2.2@6138.44,2267.36 C2.2@6138.44,2269.72
VDD3VFL: C19.2 FB1.1 U1.84 | length 503.3
  Top Layer w10: U1.84@4039.97,2998.7 v1(4123.7,2998.7) ; v1@4117.34,2992.34 ccw(c4101.97,2976.97) 4101.97,2998.7 ccw(c4101.97,3020.43) v1@4117.34,3005.07
  Bottom Layer w10: v1(4123.7,2998.7) 4152.44,3027.44 C19.2@4152.44,3040 ; v1@4123.7,3007.7 ccw(c4123.7,3029.43) 4139.07,3014.07 ccw(c4154.43,2998.7) v1@4132.7,2998.7 ; v1@4129,3004 ccw(c4098.13,3034.87) C19.2@4141.71,3037.41 ; 4144.76,3019.76 ccw(c4127.91,3036.6) C19.2@4151.69,3037.99
  Bottom Layer w20: FB1.1@4079.88,3120 4079.88,3075.12 ; C19.2@4152.44,3040 4115,3040 4079.88,3075.12 ; 4079.88,3075.12 cw(c4108.13,3075.12) 4092.09,3098.37 ccw(c4108.13,3075.12) 4079.88,3075.12 ; 4079.88,3075.12 ccw(c4051.64,3075.12) 4067.68,3098.37 cw(c4051.64,3075.12) 4079.88,3075.12
XA0: U1.151 U3.1 | length 521.6
  Top Layer w10: U1.151@5063.59,3274.29 5204.62,3274.29 5410.33,3480 U3.1@5500,3480
XA1: U1.152 U3.2 | length 773.2
  Top Layer w10: U1.152@5063.59,3293.98 5201.68,3293.98 5447.02,3539.31 5567.69,3539.31 5578,3529 5578,3458 5568.5,3448.5 U3.2@5500,3448.5
XA2: U1.153 U3.3 | length 848.6
  Top Layer w10: U1.153@5063.59,3313.66 5198.74,3313.66 5440.39,3555.31 5579.69,3555.31 5594,3541 5594,3427 5584.01,3417.01 U3.3@5500,3417.01
XA3: U1.156 U3.4 | length 905.1
  Top Layer w10: U1.156@5063.59,3372.72 5233.97,3372.72 5433.76,3572.51 5592.49,3572.51 5610,3555 5610,3404 5591.51,3385.51 U3.4@5500,3385.51
XA4: U1.157 U3.5 | length 973.4
  Top Layer w10: U1.157@5063.59,3392.4 5231.03,3392.4 5427.14,3588.51 5604.49,3588.51 5626,3567 5626,3385 5595.02,3354.02 U3.5@5500,3354.02
XA5: U1.158 U3.18 | length 1453
  Top Layer w10: U1.158@5063.59,3412.09 5228.09,3412.09 5420.51,3604.51 5628.49,3604.51 5643,3590 5643,3156.51 5626,3139.51 5626,2952 5616,2942 5502.56,2942 U3.18@5500,2944.57 ; U3.18@5529.27,2946.33 ccw(c5539.73,2956.8) 5539.73,2942
XA6: U1.161 U3.19 | length 1499.4
  Top Layer w10: U1.161@5063.59,3471.14 5261.02,3471.14 5413.88,3624 5640,3624 5659,3605 5659,3149.88 5642,3132.88 5642,2927 5628.07,2913.07 U3.19@5500,2913.07
XA7: U1.162 U3.20 | length 1571.8
  Top Layer w10: U1.162@5063.59,3490.83 5258.08,3490.83 5407.25,3640 5659,3640 5675,3624 5675,3143.25 5658,3126.25 5658,2908 5631.57,2881.57 U3.20@5500,2881.57
XA8: U1.163 U3.21 | length 1643.1
  Top Layer w10: U1.163@5063.59,3510.51 5255.14,3510.51 5400.63,3656 5666,3656 5691,3631 5691,3136.63 5674,3119.63 5674,2879 5645.08,2850.08 U3.21@5500,2850.08
XA9: U1.164 U3.22 | length 1721.3
  Top Layer w10: U1.164@5063.59,3530.2 5252.2,3530.2 5394,3672 5680,3672 5707,3645 5707,3130 5690,3113 5690,2845 5663.58,2818.58 U3.22@5500,2818.58
XA10: U1.165 U3.23 | length 1745.9
  Top Layer w10: U1.165@5063.59,3549.88 5243.51,3549.88 5381.63,3688 5762,3688 5774,3676 5774,3123.75 5821,3076.75 5821,2899 5901.42,2818.58 U3.23@5964.56,2818.58
XA11: U1.168 U3.24 | length 1721.1
  Top Layer w10: U1.168@5063.59,3608.94 5279.94,3608.94 5375,3704 5775,3704 5790,3689 5790,3130.37 5837,3083.37 5837,2913 5899.92,2850.08 U3.24@5964.56,2850.08
XA12: R17.2 U1.169 U3.25 | length 2024.5
  Top Layer w10: U1.169@5063.59,3628.62 5252.62,3628.62 v1(5273.68,3649.68) 5344,3720 5785,3720 5806,3699 5806,3137 5853,3090 5853,2932 5903.43,2881.57 U3.25@5964.56,2881.57 ; v1@5273.68,3658.68 ccw(c5273.68,3680.4) 5289.04,3665.04 ccw(c5304.4,3649.68) v1@5282.68,3649.68
  Bottom Layer w10: v1(5273.68,3649.68) 5382.76,3649.68 R17.2@5452.44,3580 ; v1@5280.04,3643.31 cw(c5295.4,3627.95) 5295.4,3649.68 cw(c5295.4,3671.4) v1@5280.04,3656.04 ; 5430.73,3601.71 ccw(c5452.44,3623.42) R17.2@5452.44,3592.72 ; 5435.48,3596.96 cw(c5420.5,3581.97) R17.2@5441.69,3581.97
XA13: R18.2 U1.172 U3.26 | length 2048.4
  Top Layer w10: U1.172@5063.59,3687.68 5249.68,3687.68 v1(5250.11,3688.11) 5298,3736 5798,3736 5822,3712 5822,3147 5869,3100 5869,2946 5901.93,2913.07 U3.26@5964.56,2913.07 ; 5227.34,3687.68 ccw(c5227.34,3710.89) v1@5243.75,3694.48 ; 5229.43,3687.68 cw(c5229.43,3667.43) v1@5243.75,3681.75 ; v1@5250.11,3697.11 ccw(c5250.11,3718.84) 5265.48,3703.48 ccw(c5280.84,3688.11) v1@5259.11,3688.11
  Bottom Layer w10: v1(5250.11,3688.11) 5404.33,3688.11 R18.2@5452.44,3640 ; v1@5256.48,3681.75 cw(c5271.84,3666.38) 5271.84,3688.11 cw(c5271.84,3709.84) v1@5256.48,3694.48 ; 5430.73,3661.71 ccw(c5452.44,3683.42) R18.2@5452.44,3652.72 ; 5435.48,3656.96 cw(c5420.5,3641.97) R18.2@5441.69,3641.97
XA14: R19.2 U1.173 U3.27 | length 1982.6
  Top Layer w10: U1.173@5063.59,3707.36 5212.36,3707.36 v1(5233.29,3728.29) 5257,3752 5815,3752 5838,3729 5838,3154.37 5885,3107.37 5885,2960 5900.43,2944.57 U3.27@5964.56,2944.57
  Bottom Layer w10: v1(5233.29,3728.29) 5424.15,3728.29 R19.2@5452.44,3700 ; v1@5239.65,3721.92 cw(c5255.01,3706.56) 5255.01,3728.29 cw(c5255.01,3750.01) v1@5239.65,3734.65 ; 5430.73,3721.71 ccw(c5452.44,3743.42) R19.2@5452.44,3712.72 ; 5435.48,3716.96 cw(c5420.5,3701.97) R19.2@5441.69,3701.97
XA15: R20.2 U1.174 U3.42 | length 1666.3
  Top Layer w10: U1.174@5063.59,3727.05 5160.05,3727.05 v1(5180.35,3747.35) 5201,3768 5827,3768 5854,3741 5854,3466 5902.99,3417.01 U3.42@5964.56,3417.01
  Bottom Layer w10: v1(5180.35,3747.35) 5209,3776 5436.44,3776 R20.2@5452.44,3760 ; v1@5180.35,3756.35 ccw(c5180.35,3778.08) 5195.71,3762.71 ccw(c5211.08,3747.35) v1@5189.35,3747.35 ; 5392.62,3776 cw(c5392.62,3702.15) R20.2@5444.84,3754.37 ; 5416.76,3776 cw(c5416.76,3726.29) R20.2@5451.91,3761.44 ; R20.2@5440.9,3776 cw(c5440.9,3750.43) R20.2@5458.98,3768.51
XA16: U1.175 U3.43 | length 1214.7
  Top Layer w10: U1.175@5063.59,3746.73 5119.36,3746.73 5156.63,3784 5838,3784 5870,3752 5870,3480 5901.5,3448.5 U3.43@5964.56,3448.5
XA17: U1.176 U3.44 | length 1201.8
  Top Layer w10: U1.176@5063.59,3766.42 5116.42,3766.42 5150,3800 5908,3800 5964.56,3743.44 U3.44@5964.56,3480
XA18: U1.1 U3.28 | length 2314.3
  Top Layer w10: U1.1@4975,3855 5028,3855 5072,3899 6046,3899 6115,3830 v1(6115,3308) ; U3.28@5964.56,2976.06 v1(6058.94,2976.06) ; v1@6052.57,2969.7 ccw(c6037.21,2954.33) 6037.21,2976.06 ccw(c6037.21,2997.79) v1@6052.57,2982.43 ; v1@6108.64,3314.36 ccw(c6093.27,3329.73) 6115,3329.73 ccw(c6136.73,3329.73) v1@6121.36,3314.36
  Bottom Layer w10: v1(6058.94,2976.06) 6092.06,2976.06 6115,2999 v1(6115,3308) ; v1@6065.3,2969.7 cw(c6080.67,2954.33) 6080.67,2976.06 cw(c6080.67,2997.79) v1@6065.3,2982.43 ; v1@6108.64,3301.64 cw(c6093.27,3286.27) 6115,3286.27 cw(c6136.73,3286.27) v1@6121.36,3301.64
XCLKOUT: JP2.8 U1.138 | length 1543.5
  Top Layer w10: v1(4960,2985) 4993.39,3018.39 U1.138@5063.59,3018.39 ; v1@4960,2994 ccw(c4960,3015.73) 4975.36,3000.36 ccw(c4990.73,2985) v1@4969,2985
  Bottom Layer w10: JP2.8@4935.47,1820 ccw(c4876.26,1820) 4918.13,1861.87 ccw(c4960,1903.74) JP2.8@4960,1844.53 ; JP2.8@4945.47,1820 ccw(c4910.4,1820) 4935.2,1844.8 ccw(c4960,1869.6) JP2.8@4960,1834.53 ; v1@4951,2985 cw(c4929.27,2985) 4944.64,2969.64 cw(c4960,2954.27) v1@4960,2976 ; JP2.8@4960,1820 4906,1874 4906,2931 v1(4960,2985)
XD0: U1.136 U3.7 | length 646.5
  Top Layer w10: U1.136@5063.59,2979.02 5194.02,2979.02 5280,3065 5280,3203.02 5368,3291.02 U3.7@5500,3291.02
XD1: U1.135 U3.8 | length 646
  Top Layer w10: U1.135@5063.59,2959.33 5067.27,2963.02 5200.65,2963.02 5296,3058.37 5296,3187 5368.53,3259.53 U3.8@5500,3259.53 ; U1.135@5096.59,2959.33 cw(c5105.48,2950.43) 5105.48,2963.02
XD2: U1.134 U3.9 | length 634.4
  Top Layer w10: U1.134@5063.59,2939.65 5067.27,2943.33 5203.59,2943.33 5312,3051.75 5312,3169 5371.03,3228.03 U3.9@5500,3228.03 ; U1.134@5096.59,2939.65 cw(c5105.48,2930.75) 5105.48,2943.33
XD3: U1.133 U3.10 | length 612.4
  Top Layer w10: U1.133@5063.59,2919.96 5202.84,2919.96 5328,3045.12 5328,3150 5374.54,3196.54 U3.10@5500,3196.54
XD4: U1.132 U3.13 | length 637.1
  Top Layer w10: U1.132@4975,2831.38 5136.89,2831.38 5407.56,3102.05 U3.13@5500,3102.05
XD5: U1.131 U3.14 | length 724.9
  Top Layer w10: U1.131@4955.32,2831.38 4955.32,2779.68 4965,2770 5098.14,2770 5398.14,3070 5499.45,3070 U3.14@5500,3070.55
XD6: U1.130 U3.15 | length 757.1
  Top Layer w10: U1.130@4935.63,2831.38 4935.63,2764.37 4950,2750 5105,2750 5394.05,3039.05 U3.15@5500,3039.05
XD7: U1.129 U3.16 | length 790.5
  Top Layer w10: U1.129@4915.95,2831.38 4915.95,2754.05 4945,2725 5105,2725 5387.56,3007.56 U3.16@5500,3007.56
XD8: U1.128 U3.29 | length 1763.3
  Top Layer w10: U1.128@4896.26,2798.38 cw(c4887.37,2789.49) 4899.95,2789.49 ; U1.128@4896.26,2831.38 4899.95,2827.7 4899.95,2747.43 4947.37,2700 6065,2700 6140,2775 6140,2955 6087.44,3007.56 U3.29@5964.56,3007.56
XD9: U1.127 U3.30 | length 1842.3
  Top Layer w10: U1.127@4876.58,2831.38 4876.58,2748.17 4940.75,2684 6071.63,2684 6156,2768.37 6156,2964 6080.95,3039.05 U3.30@5964.56,3039.05
XD10: U1.124 U3.31 | length 2005.9
  Top Layer w10: U1.124@4817.52,2831.38 4817.52,2682.48 4832,2668 6078.25,2668 6172,2761.75 6172,2970.63 6072.08,3070.55 U3.31@5964.56,3070.55
XD11: U1.123 U3.32 | length 2103.3
  Top Layer w10: U1.123@4797.84,2798.38 cw(c4788.94,2789.48) 4801.52,2789.48 ; U1.123@4797.84,2831.38 4801.52,2827.69 4801.52,2675.85 4825.37,2652 6084.88,2652 6188,2755.12 6188,2977.25 6063.21,3102.05 U3.32@5964.56,3102.05
XD12: U1.122 U3.35 | length 2273.7
  Top Layer w10: U1.122@4778.15,2798.38 cw(c4769.26,2789.49) 4781.84,2789.49 ; U1.122@4778.15,2831.38 4781.84,2827.7 4781.84,2672.91 4818.75,2636 6091.51,2636 6204,2748.49 6204,3081 6088.46,3196.54 U3.35@5964.56,3196.54
XD13: U1.119 U3.36 | length 2404
  Top Layer w10: U1.119@4719.1,2831.38 4719.1,2650.9 4750,2620 6098.14,2620 6220,2741.86 6220,3087.63 6079.6,3228.03 U3.36@5964.56,3228.03
XD14: U1.116 U3.37 | length 2535.5
  Top Layer w10: U1.116@4660.04,2831.38 4660.04,2639.96 4696,2604 6104.76,2604 6236,2735.24 6236,3094.25 6070.73,3259.53 U3.37@5964.56,3259.53
XD15: U1.115 U3.38 | length 2630.3
  Top Layer w10: U1.115@4640.36,2831.38 4640.36,2624.64 4677,2588 6111.39,2588 6252,2728.61 6252,3100.88 6061.86,3291.02 U3.38@5964.56,3291.02
XRDN: U1.149 U3.41 | length 1099.9
  Top Layer w10: U1.149@5063.59,3234.92 v1(5242.92,3234.92) ; v1@5236.56,3228.56 ccw(c5221.19,3213.19) 5221.19,3234.92 ccw(c5221.19,3256.65) v1@5236.56,3241.29 ; v1(5879,3385) 5879.51,3385.51 U3.41@5964.56,3385.51 ; v1@5885.36,3378.64 cw(c5901.96,3362.04) 5901.96,3385.51 ; v1@5885.36,3391.36 ccw(c5899.49,3405.49) 5899.49,3385.51
  Bottom Layer w10: v1(5242.92,3234.92) 5393,3385 v1(5879,3385) ; v1@5242.92,3243.92 ccw(c5242.92,3265.65) 5258.29,3250.29 ccw(c5273.65,3234.92) v1@5251.92,3234.92 ; v1@5872.64,3378.64 ccw(c5857.27,3363.27) 5857.27,3385 ccw(c5857.27,3406.73) v1@5872.64,3391.36
XREADY: U1.142
XRSN: C1.2 R5.1 S1.1 U1.80 | length 1975.6
  Top Layer w10: C1.2@3521.5,2190 R5.1@3682.44,2190 ; C1.2@3531.88,2179.62 cw(c3556.95,2154.55) 3556.95,2190 cw(c3556.95,2225.45) C1.2@3531.88,2200.38 ; R5.1@3674.84,2180.43 cw(c3656.49,2162.08) 3682.44,2162.08 cw(c3708.39,2162.08) R5.1@3690.04,2180.43 ; R5.1@3674.84,2182.4 ccw(c3656.49,2164.05) 3656.49,2190 ccw(c3656.49,2215.95) R5.1@3674.84,2197.6 ; R5.1@3674.84,2199.57 ccw(c3656.49,2217.92) 3682.44,2217.92 ccw(c3708.39,2217.92) R5.1@3690.04,2199.57 ; 3682.44,2215.02 cw(c3729.98,2215.02) v1@3696.36,2248.64 ; 3682.44,2239.17 cw(c3705.83,2239.17) v1@3689.29,2255.71 ; v1@3682.44,2247.44 R5.1@3682.44,2190 ; S1.1@3745.93,2066.83 ccw(c3714.14,2035.04) 3714.14,2080 ccw(c3714.14,2124.96) S1.1@3745.93,2093.17 ; S1.1@3765,2080 3710,2080 3682.44,2107.56 R5.1@3682.44,2190 ; v1@3921.29,3066.71 cw(c3947.21,3040.79) 3947.21,3077.44 ; v1(3922,3066) 3933.44,3077.44 U1.80@4039.97,3077.44 ; v1@3928.36,3059.64 cw(c3971.35,3016.65) 3971.35,3077.44
  Bottom Layer w10: v1(3690,2255) 3720,2285 3894,2285 3922,2313 v1(3922,3066) ; v1@3690,2264 ccw(c3690,2285.73) 3705.36,2270.36 ccw(c3720.73,2255) v1@3699,2255 ; v1@3915.64,3059.64 cw(c3900.27,3044.27) 3922,3044.27 cw(c3943.73,3044.27) v1@3928.36,3059.64
XWEN: U1.137 U3.17 | length 704.5
  Top Layer w10: U1.137@5063.59,2998.7 5147.7,2998.7 v1(5238.5,3089.5) ; v1@5229.5,3089.5 cw(c5207.77,3089.5) 5223.14,3074.14 cw(c5238.5,3058.77) v1@5238.5,3080.5 ; v1@5409.06,2976.06 U3.17@5500,2976.06 ; v1@5421.36,2969.64 cw(c5436.88,2954.12) 5436.88,2976.06 ; v1@5421.36,2982.36 ccw(c5436.58,2997.58) 5436.58,2976.06
  Bottom Layer w10: v1(5238.5,3089.5) 5303.5,3089.5 5331,3062 5331,2992 5347,2976 v1(5415,2976) ; v1@5244.86,3083.14 cw(c5260.23,3067.77) 5260.23,3089.5 cw(c5260.23,3111.23) v1@5244.86,3095.86 ; v1@5408.64,2969.64 ccw(c5393.27,2954.27) 5393.27,2976 ccw(c5393.27,2997.73) v1@5408.64,2982.36
XZCS7N: U1.150 U3.6 | length 464.5
  Top Layer w10: U1.150@5063.59,3254.61 5207.57,3254.61 5275.48,3322.52 U3.6@5500,3322.52
pads on no net: Designator34.0 Designator35.0 J11.6 U1.2 U1.5 U1.7 U1.11 U1.13 U1.16 U1.17 U1.19 U1.26 U1.27 U1.28 U1.35 U1.36 U1.37 U1.38 U1.39 U1.40 U1.41 U1.42 U1.46 U1.47 U1.48 U1.49 U1.50 U1.51 U1.52 U1.53 U1.62 U1.63 U1.68 U1.69 U1.72 U1.73 U1.74 U1.75 U1.81 U1.82 U1.88 U1.89 U1.99 U1.100 U1.110 U1.111 U1.112 U1.141 U2.1 U2.2 U2.7 U2.8 U2.13 U2.14 U2.15 U2.16 U2.17 U2.20 U2.21 U2.22 U2.26 U2.27 U2.28

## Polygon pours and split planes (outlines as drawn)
+3.3V on Top Layer "Keep-Out Layer-No Net" (solid, pour order 1000): 3450,3845 3635,3845 3635,3660 3495,3660 3450,3705 3440,3715 3440,3780 3440,3845 3450,3845
GND on GND (split plane): 6259.89,1763.11 3300.11,1763.11 3300.11,4219.89 6259.89,4219.89
AGND on GND (split plane): 4377.91,3500.09 4210,3500.09 4207.39,3499.74 4204.96,3498.74 4202.87,3497.13 4201.27,3495.04 4200.26,3492.61 4199.91,3490 4199.91,3475.09 4125.09,3475.09 4125.09,3490 4124.74,3492.61 4123.73,3495.04 4122.13,3497.13 4120.04,3498.74 4117.61,3499.74 4115,3500.09 3975,3500.09 3972.39,3499.74 3969.96,3498.74 3967.87,3497.13 3966.26,3495.04 3965.26,3492.61 3964.91,3490 3964.91,3455.09 3620.09,3455.09 3620.09,3629.91 3765,3629.91 3767.61,3630.26 3770.04,3631.26 3772.13,3632.87 3773.74,3634.96 3774.74,3637.39 3775.09,3640 3775.09,3650 3775.09,4056.91 4377.91,4056.91
+3.3V on POWER (split plane): 6259.89,1763.11 3300.11,1763.11 3300.11,4219.89 6259.89,4219.89
+1.9V on POWER (split plane): 173 vertices, not listed, extent 4220.09,2003.09 5164.91,3884.91
+3.3VA on POWER (split plane): 3999.91,3860 4000.26,3857.39 4001.26,3854.96 4002.87,3852.87 4004.96,3851.26 4007.39,3850.26 4010,3849.91 4085,3849.91 4087.61,3850.26 4090.04,3851.26 4092.13,3852.87 4093.74,3854.96 4094.74,3857.39 4095.09,3860 4095.09,3884.91 4384.91,3884.91 4384.91,3765.09 4265,3765.09 4262.39,3764.74 4259.96,3763.74 4257.87,3762.13 4256.27,3760.04 4255.26,3757.61 4254.91,3755 4254.91,3655.09 4000,3655.09 3997.39,3654.74 3994.96,3653.74 3992.87,3652.13 3991.26,3650.04 3990.26,3647.61 3989.91,3645 3989.91,3485.09 3825.09,3485.09 3825.09,3979.91 3999.91,3979.91
+1.9VA on POWER (split plane): 4384.91,3500.09 4210,3500.09 4207.39,3499.74 4204.96,3498.74 4202.87,3497.13 4201.27,3495.04 4200.26,3492.61 4199.91,3490 4199.91,3315.09 4010.09,3315.09 4010.09,3634.91 4265,3634.91 4267.61,3635.26 4270.04,3636.26 4272.13,3637.87 4273.73,3639.96 4274.74,3642.39 4275.09,3645 4275.09,3744.91 4384.91,3744.91

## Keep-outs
Keep-Out Layer:
  lines w10: 3275,1738 6282,1738 6285,1741 6285,4244 6284,4245 3275,4245 3275,1738

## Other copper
Top Layer:
  region net +3.3V: 5125,2514 4960,2514 4960,2309 5125,2309
  region net +1.9V: 5121,2213 4956,2213 4956,2008 5121,2008
  rectangle net AGND: 3880,3840 3950,3955
  rectangle net +3.3VA: 3850,3735 3950,3825
  rectangle net GND: 3372,3855 3610,3925
GND (plane layer: these items are gaps in the copper):
  lines w6: 3975,3480 3975,3490
  lines w20: 3610,3445 3610,3640 3710,3640 3765,3640 3765,3650 3765,4067 4388,4067 4388,3492 ; 3620,3445 3730,3445 ; 3710,3445 3975,3445 3975,3490 4115,3490 4115,3465 4210,3465 4210,3490 4390,3490
POWER (plane layer: these items are gaps in the copper):
  lines w10: 4526,2799 4554,2799 ; 4553,2548 4554,2549 ; 4665,2797 4712,2797 ; 4867,2647 4868,2646
  lines w20: 4000,3475 3815,3475 3815,3990 4010,3990 4010,3860 4085,3860 4085,3895 4395,3895 ; 4395,3755 4265,3755 4265,3645 4000,3645 4000,3305 4210,3305 ; 4525,2800 4525,2915 4490,2950 4490,2985 4415,2985 4415,2800 4305,2800 4305,3305 4210,3305 ; 4553,2548 4749,2548 4749,1993 5173,1993 ; 4554,2549 4554,2799 ; 4665,2797 4665,2647 4867,2647 ; 4715,2800 4715,2965 4815,2965 4815,2800 5070,2800 5090,2800 5090,2860 ; 4868,2646 4868,2230 5175,2230 5175,1993 ; 5090,2840 5090,3080 4925,3080 4925,3145 5090,3145 5090,3420 4925,3420 4925,3500 5095,3500 5095,3620 4960,3620 4960,3675 5120,3675 ; 5121,3679 5121,3890 4870,3890 4870,3725 4765,3725 4765,3895 4395,3895 ; 4210,3305 4210,3490 4395,3490 4395,3895

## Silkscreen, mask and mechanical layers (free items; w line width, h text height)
Mechanical 1:
  lines w10: 3273,1736 6286,1736 6286,4247 3273,4247 3273,1736

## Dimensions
6284,4245 to 6282,1738 on Top Layer
3275,1738 to 6285,1741 on Top Layer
